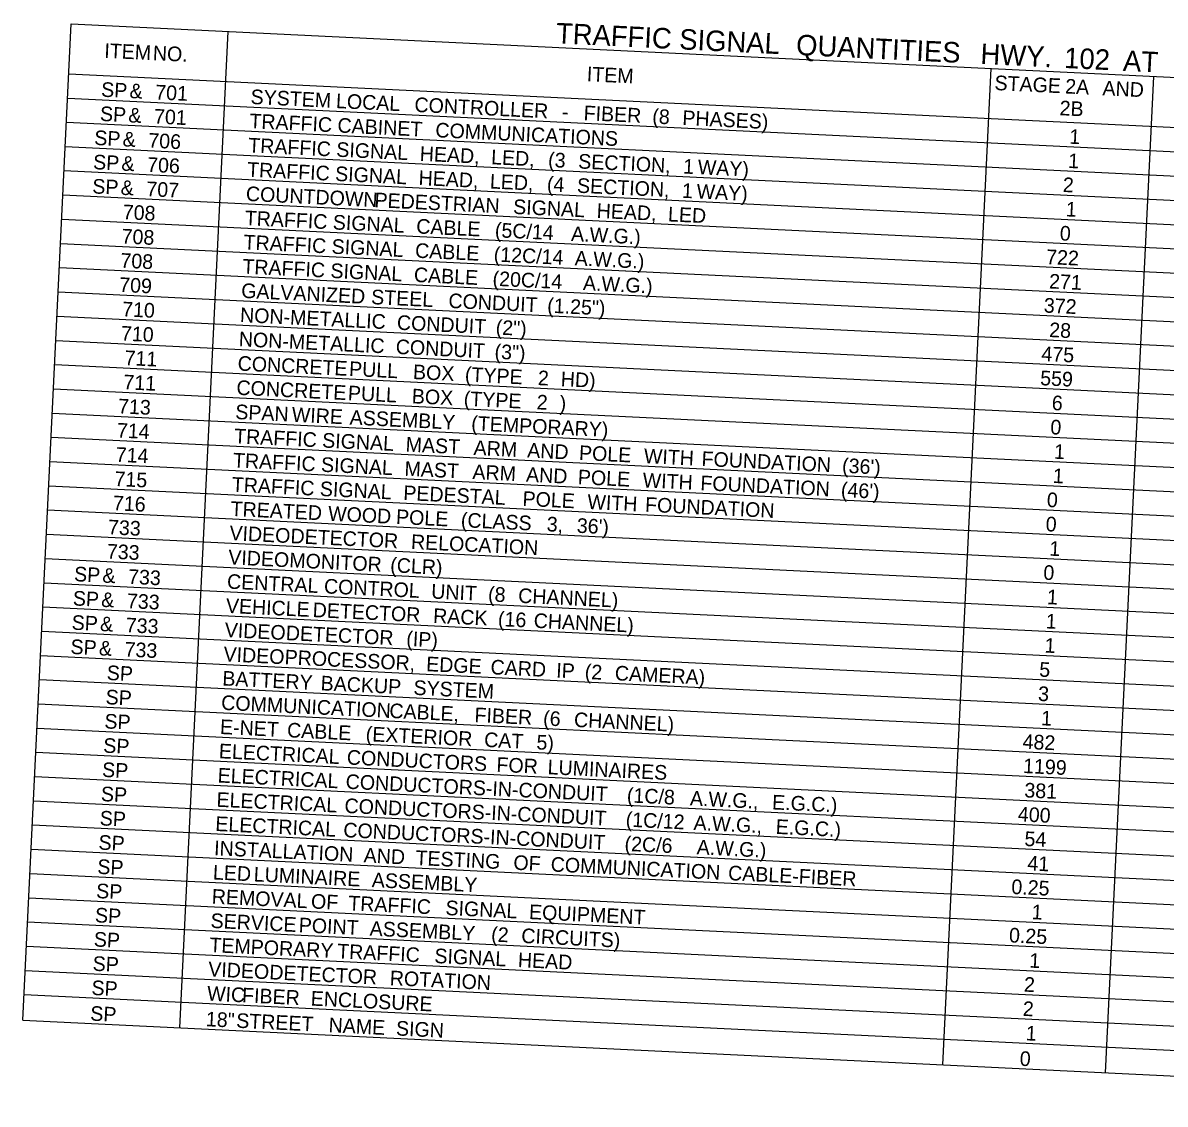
# Model space of a CAD drawing. Extents: x 669100 to 670801, y 741155 to 743955.
# Drawn here: x 669390.2 to 669585.2, y 743447.8 to 743632.5 of the extents above; entities that cross this region are included whole.
import ezdxf

# ---------------------------------------------------------------- set-up
doc = ezdxf.new("R2010")
doc.units = 0
doc.layers.add('R_Dimension', color=7, linetype='Continuous')

msp = doc.modelspace()

# ---------------------------------------------------------------- linework, layer by layer
at = {"layer": 'R_Dimension'}
for p, q in [((669390.25, 743462.16), (669398.51, 743632.34)), ((669398.51, 743632.34), (669693.59, 743618.01)), ((669417.03, 743460.86), (669425.29, 743631.04)), ((669398.1, 743623.82), (669693.18, 743609.49)), ((669547.28, 743454.54), (669555.55, 743624.72)), ((669575.04, 743453.19), (669583.3, 743623.37)), ((669397.9, 743619.68), (669692.97, 743605.35)), ((669397.7, 743615.54), (669692.77, 743601.21)), ((669397.49, 743611.4), (669692.57, 743597.08)), ((669397.29, 743607.27), (669692.37, 743592.94)), ((669397.09, 743603.13), (669692.17, 743588.8)), ((669396.89, 743598.99), (669691.97, 743584.66)), ((669396.69, 743594.85), (669691.77, 743580.52)), ((669396.49, 743590.71), (669691.57, 743576.38)), ((669396.29, 743586.57), (669691.37, 743572.24)), ((669396.09, 743582.43), (669691.17, 743568.1)), ((669395.89, 743578.29), (669690.96, 743563.96)), ((669395.69, 743574.15), (669690.76, 743559.83)), ((669395.49, 743570.02), (669690.56, 743555.69)), ((669395.28, 743565.88), (669690.36, 743551.55)), ((669395.08, 743561.74), (669690.16, 743547.41)), ((669394.88, 743557.6), (669689.96, 743543.27)), ((669394.68, 743553.46), (669689.76, 743539.13)), ((669394.48, 743549.32), (669689.56, 743534.99)), ((669394.28, 743545.18), (669689.36, 743530.85)), ((669394.08, 743541.04), (669689.16, 743526.71)), ((669393.88, 743536.9), (669688.95, 743522.58)), ((669393.68, 743532.77), (669688.75, 743518.44)), ((669393.48, 743528.63), (669688.55, 743514.3)), ((669393.27, 743524.49), (669688.35, 743510.16)), ((669393.07, 743520.35), (669688.15, 743506.02)), ((669392.87, 743516.21), (669687.95, 743501.88)), ((669392.67, 743512.07), (669687.75, 743497.74)), ((669392.47, 743507.93), (669687.55, 743493.6)), ((669392.27, 743503.79), (669687.35, 743489.46)), ((669392.07, 743499.65), (669687.15, 743485.33)), ((669391.87, 743495.52), (669686.94, 743481.19)), ((669391.67, 743491.38), (669686.74, 743477.05)), ((669391.47, 743487.24), (669686.54, 743472.91)), ((669391.26, 743483.1), (669686.34, 743468.77)), ((669391.06, 743478.96), (669686.14, 743464.63)), ((669390.86, 743474.82), (669685.94, 743460.49)), ((669390.66, 743470.68), (669685.74, 743456.35)), ((669390.46, 743466.54), (669685.54, 743452.22)), ((669390.25, 743462.16), (669685.33, 743447.83))]:
    msp.add_line(p, q, dxfattribs=at)

# ---------------------------------------------------------------- texts
for s, height, p in [('TRAFFIC', 3.5, (669481.19, 743629.03)), (' SIGNAL', 3.5, (669500.93, 743628.07)), ('ITEM', 2.5, (669404.11, 743626.55)), (' QUANTITIES', 3.5, (669520.88, 743627.1)), (' HWY.', 3.5, (669552.35, 743625.57)), (' NO.', 2.5, (669411.47, 743626.19)), (' 102', 3.5, (669566.63, 743624.88)), (' AT', 3.5, (669576.68, 743624.39)), ('ITEM', 2.5, (669486.47, 743622.55)), ('STAGE', 2.5, (669556.07, 743621.05)), (' 2A', 2.5, (669567.2, 743620.51)), ('SP', 2.5, (669403.57, 743619.91)), (' &', 2.5, (669407.49, 743619.72)), (' 701', 2.5, (669411.87, 743619.5)), ('SYSTEM', 2.5, (669429.08, 743618.67)), (' AND', 2.5, (669573.57, 743620.2)), (' LOCAL', 2.5, (669442.73, 743618.01)), (' CONTROLLER', 2.5, (669456.12, 743617.36)), ('2B', 2.5, (669567.17, 743616.75)), ('SP', 2.5, (669403.37, 743615.77)), (' &', 2.5, (669407.29, 743615.58)), (' 701', 2.5, (669411.67, 743615.37)), (' -', 2.5, (669481.29, 743616.13)), (' FIBER', 2.5, (669485, 743615.95)), (' (8', 2.5, (669496.72, 743615.38)), (' PHASES)', 2.5, (669501.85, 743615.13)), ('TRAFFIC', 2.5, (669428.88, 743614.53)), (' CABINET', 2.5, (669442.98, 743613.84)), (' COMMUNICATIONS', 2.5, (669459.69, 743613.03)), ('SP', 2.5, (669402.4, 743611.67)), (' &', 2.5, (669406.31, 743611.48)), (' 706', 2.5, (669410.69, 743611.26)), ('1', 2.5, (669568.83, 743611.88)), ('TRAFFIC', 2.5, (669428.68, 743610.39)), (' SIGNAL', 2.5, (669442.78, 743609.71)), (' HEAD,', 2.5, (669457.03, 743609.01)), ('SP', 2.5, (669402.2, 743607.53)), (' &', 2.5, (669406.11, 743607.34)), (' 706', 2.5, (669410.49, 743607.13)), (' LED,', 2.5, (669469.21, 743608.42)), (' (3', 2.5, (669478.94, 743607.95)), (' SECTION,', 2.5, (669484.07, 743607.7)), ('1', 2.5, (669568.63, 743607.74)), ('TRAFFIC', 2.5, (669428.48, 743606.25)), (' SIGNAL', 2.5, (669442.58, 743605.57)), (' 1', 2.5, (669501.98, 743606.83)), (' WAY)', 2.5, (669504.48, 743606.71)), ('SP', 2.5, (669402.06, 743603.39)), (' &', 2.5, (669405.98, 743603.2)), (' 707', 2.5, (669410.36, 743602.98)), (' HEAD,', 2.5, (669456.83, 743604.87)), (' LED,', 2.5, (669469, 743604.28)), (' (4', 2.5, (669478.74, 743603.81)), (' SECTION,', 2.5, (669483.87, 743603.56)), ('2', 2.5, (669567.72, 743603.64)), ('COUNTDOWN', 2.5, (669428.28, 743602.11)), (' PEDESTRIAN', 2.5, (669449.3, 743601.09)), (' 1', 2.5, (669501.78, 743602.69)), (' WAY)', 2.5, (669504.28, 743602.57)), (' SIGNAL', 2.5, (669472.97, 743599.94)), (' HEAD,', 2.5, (669487.23, 743599.25)), ('1', 2.5, (669568.23, 743599.47)), ('708', 2.5, (669407.26, 743598.99)), ('TRAFFIC', 2.5, (669428.08, 743597.97)), (' SIGNAL', 2.5, (669442.18, 743597.29)), (' LED', 2.5, (669499.4, 743598.66)), (' CABLE', 2.5, (669456.43, 743596.6)), (' (5C/14', 2.5, (669469.86, 743595.95)), (' A.W.G.)', 2.5, (669482.86, 743595.31)), ('0', 2.5, (669567.21, 743595.37)), ('708', 2.5, (669407.06, 743594.85)), ('TRAFFIC', 2.5, (669427.88, 743593.84)), (' SIGNAL', 2.5, (669441.98, 743593.15)), (' CABLE', 2.5, (669456.23, 743592.46)), (' (12C/14', 2.5, (669469.66, 743591.81)), ('722', 2.5, (669564.88, 743591.33)), ('708', 2.5, (669406.86, 743590.71)), ('TRAFFIC', 2.5, (669427.68, 743589.7)), (' A.W.G.)', 2.5, (669483.48, 743591.14)), (' SIGNAL', 2.5, (669441.78, 743589.01)), (' CABLE', 2.5, (669456.03, 743588.32)), (' (20C/14', 2.5, (669469.46, 743587.67)), ('709', 2.5, (669406.65, 743586.57)), ('GALVANIZED', 2.5, (669427.48, 743585.56)), (' A.W.G.)', 2.5, (669484.89, 743586.92)), ('271', 2.5, (669565.38, 743587.16)), (' STEEL', 2.5, (669448.73, 743584.53)), (' CONDUIT', 2.5, (669461.92, 743583.88)), ('710', 2.5, (669407.15, 743582.4)), (' (1.25")', 2.5, (669478.79, 743583.07)), ('372', 2.5, (669564.48, 743583.05)), ('NON-METALLIC', 2.5, (669427.28, 743581.42)), (' CONDUIT', 2.5, (669453.13, 743580.16)), ('710', 2.5, (669406.95, 743578.26)), (' (2")', 2.5, (669470, 743579.34)), ('28', 2.5, (669565.4, 743578.86)), ('NON-METALLIC', 2.5, (669427.07, 743577.28)), (' CONDUIT', 2.5, (669452.93, 743576.02)), ('711', 2.5, (669407.57, 743574.08)), (' (3")', 2.5, (669469.8, 743575.2)), ('475', 2.5, (669564.07, 743574.78)), ('CONCRETE', 2.5, (669426.87, 743573.14)), (' PULL', 2.5, (669444.96, 743572.26)), ('711', 2.5, (669407.37, 743569.94)), (' BOX', 2.5, (669455.87, 743571.73)), (' (TYPE', 2.5, (669464.74, 743571.3)), (' 2', 2.5, (669477.19, 743570.7)), (' HD)', 2.5, (669481.1, 743570.51)), ('559', 2.5, (669563.86, 743570.64)), ('CONCRETE', 2.5, (669426.67, 743569)), (' PULL', 2.5, (669444.76, 743568.12)), (' BOX', 2.5, (669455.67, 743567.59)), (' (TYPE', 2.5, (669464.54, 743567.16)), (' 2', 2.5, (669476.99, 743566.56)), (' )', 2.5, (669480.9, 743566.37)), ('6', 2.5, (669565.84, 743566.39)), ('713', 2.5, (669406.46, 743565.83)), ('SPAN', 2.5, (669426.47, 743564.86)), (' WIRE', 2.5, (669435.18, 743564.44)), (' ASSEMBLY', 2.5, (669445.07, 743563.96)), (' (TEMPORARY)', 2.5, (669465.82, 743562.95)), ('0', 2.5, (669565.6, 743562.26)), ('714', 2.5, (669406.26, 743561.7)), ('TRAFFIC', 2.5, (669426.27, 743560.72)), (' SIGNAL', 2.5, (669440.37, 743560.04)), (' MAST', 2.5, (669454.62, 743559.35)), (' ARM', 2.5, (669466.22, 743558.78)), (' AND', 2.5, (669475.37, 743558.34)), ('714', 2.5, (669406.06, 743557.56)), ('TRAFFIC', 2.5, (669426.07, 743556.59)), (' POLE', 2.5, (669484.21, 743557.91)), (' WITH', 2.5, (669495.28, 743557.37)), (' FOUNDATION', 2.5, (669505.13, 743556.89)), ('1', 2.5, (669566.22, 743558.08)), (' SIGNAL', 2.5, (669440.17, 743555.9)), (' MAST', 2.5, (669454.42, 743555.21)), (' ARM', 2.5, (669466.02, 743554.65)), (" (36')", 2.5, (669529.12, 743555.73)), ('715', 2.5, (669405.85, 743553.42)), ('TRAFFIC', 2.5, (669425.87, 743552.45)), (' AND', 2.5, (669475.17, 743554.2)), (' POLE', 2.5, (669484.01, 743553.77)), (' WITH', 2.5, (669495.08, 743553.23)), (' FOUNDATION', 2.5, (669504.93, 743552.76)), ('1', 2.5, (669566.02, 743553.94)), (' SIGNAL', 2.5, (669439.97, 743551.76)), (' PEDESTAL', 2.5, (669454.22, 743551.07)), (" (46')", 2.5, (669528.92, 743551.59)), ('716', 2.5, (669405.58, 743549.28)), ('TREATED', 2.5, (669425.67, 743548.31)), (' POLE', 2.5, (669474.57, 743550.08)), (' WITH', 2.5, (669485.64, 743549.54)), (' FOUNDATION', 2.5, (669495.49, 743549.07)), ('0', 2.5, (669565, 743549.84)), (' WOOD', 2.5, (669441.38, 743547.54)), (' POLE', 2.5, (669452.98, 743546.98)), (' (CLASS', 2.5, (669464.05, 743546.44)), ('733', 2.5, (669404.74, 743545.17)), (' 3,', 2.5, (669478.7, 743545.73)), (" 36')", 2.5, (669483.83, 743545.48)), ('0', 2.5, (669564.8, 743545.7)), ('VIDEO', 2.5, (669425.47, 743544.17)), (' DETECTOR', 2.5, (669434.96, 743543.71)), (' RELOCATION', 2.5, (669455.53, 743542.71)), ('733', 2.5, (669404.54, 743541.04)), ('1', 2.5, (669565.42, 743541.52)), ('VIDEO', 2.5, (669425.27, 743540.03)), (' MONITOR', 2.5, (669434.76, 743539.57)), (' (CLR)', 2.5, (669451.99, 743538.73)), ('SP', 2.5, (669398.95, 743537.16)), (' &', 2.5, (669402.86, 743536.97)), (' 733', 2.5, (669407.24, 743536.76)), ('0', 2.5, (669564.4, 743537.42)), ('CENTRAL', 2.5, (669425.06, 743535.89)), (' CONTROL', 2.5, (669440.68, 743535.13)), ('SP', 2.5, (669398.74, 743533.02)), (' &', 2.5, (669402.66, 743532.83)), (' UNIT', 2.5, (669458.98, 743534.24)), (' (8', 2.5, (669468.69, 743533.77)), (' CHANNEL)', 2.5, (669473.83, 743533.52)), ('1', 2.5, (669565.01, 743533.24)), (' 733', 2.5, (669407.04, 743532.62)), ('VEHICLE', 2.5, (669424.86, 743531.75)), (' DETECTOR', 2.5, (669438.75, 743531.08)), ('SP', 2.5, (669398.54, 743528.88)), (' RACK', 2.5, (669459.31, 743530.08)), (' (16', 2.5, (669470.38, 743529.54)), (' CHANNEL)', 2.5, (669476.48, 743529.25)), ('1', 2.5, (669564.81, 743529.1)), (' &', 2.5, (669402.46, 743528.69)), (' 733', 2.5, (669406.84, 743528.48)), ('VIDEO', 2.5, (669424.66, 743527.61)), (' DETECTOR', 2.5, (669434.16, 743527.15)), (' (IP)', 2.5, (669454.73, 743526.15)), ('1', 2.5, (669564.61, 743524.97)), ('SP', 2.5, (669398.34, 743524.74)), (' &', 2.5, (669402.26, 743524.55)), (' 733', 2.5, (669406.64, 743524.34)), ('VIDEO', 2.5, (669424.46, 743523.47)), (' PROCESSOR,', 2.5, (669433.96, 743523.01)), (' EDGE', 2.5, (669458.12, 743521.84)), (' CARD', 2.5, (669469.11, 743521.31)), ('SP', 2.5, (669404.53, 743520.29)), ('BATTERY', 2.5, (669424.26, 743519.34)), (' IP', 2.5, (669480.32, 743520.76)), (' (2', 2.5, (669485.2, 743520.52)), (' CAMERA)', 2.5, (669490.33, 743520.28)), ('5', 2.5, (669563.7, 743520.86)), (' BACKUP', 2.5, (669440.11, 743518.57)), (' SYSTEM', 2.5, (669455.96, 743517.8)), ('SP', 2.5, (669404.33, 743516.15)), ('COMMUNICATION', 2.5, (669424.06, 743515.2)), ('3', 2.5, (669563.5, 743516.72)), (' CABLE,', 2.5, (669451.84, 743513.85)), ('SP', 2.5, (669404.13, 743512.02)), (' FIBER', 2.5, (669466.37, 743513.14)), (' (6', 2.5, (669478.09, 743512.57)), (' CHANNEL)', 2.5, (669483.36, 743512.32)), ('1', 2.5, (669564.01, 743512.55)), ('E-NET', 2.5, (669423.86, 743511.06)), (' CABLE', 2.5, (669434.38, 743510.55)), (' (EXTERIOR', 2.5, (669447.81, 743509.89)), ('SP', 2.5, (669403.93, 743507.88)), (' CAT', 2.5, (669468.02, 743508.91)), (' 5)', 2.5, (669476.95, 743508.48)), ('482', 2.5, (669560.86, 743508.55)), ('ELECTRICAL', 2.5, (669423.66, 743506.92)), (' CONDUCTORS', 2.5, (669444.58, 743505.9)), ('SP', 2.5, (669403.73, 743503.74)), (' FOR', 2.5, (669470.12, 743504.66)), (' LUMINAIRES', 2.5, (669478.85, 743504.24)), ('1199', 2.5, (669560.94, 743504.4)), ('ELECTRICAL', 2.5, (669423.46, 743502.78)), (' CONDUCTORS-IN-CONDUIT', 2.5, (669444.38, 743501.76)), ('SP', 2.5, (669403.53, 743499.6)), ('381', 2.5, (669561.16, 743500.24)), ('ELECTRICAL', 2.5, (669423.26, 743498.64)), (' (1C/8', 2.5, (669492.39, 743499.43)), (' A.W.G.,', 2.5, (669503.15, 743498.91)), (' E.G.C.)', 2.5, (669517.17, 743498.23)), (' CONDUCTORS-IN-CONDUIT', 2.5, (669444.18, 743497.63)), ('400', 2.5, (669560.05, 743496.15)), ('SP', 2.5, (669403.33, 743495.46)), ('ELECTRICAL', 2.5, (669423.06, 743494.5)), (' (1C/12', 2.5, (669492.19, 743495.29)), (' A.W.G.,', 2.5, (669503.77, 743494.73)), (' E.G.C.)', 2.5, (669517.79, 743494.05)), (' CONDUCTORS-IN-CONDUIT', 2.5, (669443.98, 743493.49)), ('54', 2.5, (669561.18, 743491.94)), ('SP', 2.5, (669403.12, 743491.32)), ('INSTALLATION', 2.5, (669422.85, 743490.36)), (' (2C/6', 2.5, (669491.99, 743491.15)), (' A.W.G.)', 2.5, (669504.3, 743490.56)), (' AND', 2.5, (669447.45, 743489.17)), (' TESTING', 2.5, (669456.3, 743488.74)), (' OF', 2.5, (669473.01, 743487.93)), ('SP', 2.5, (669402.92, 743487.18)), ('LED', 2.5, (669422.65, 743486.22)), (' COMMUNICATION', 2.5, (669479.38, 743487.62)), (' CABLE-FIBER', 2.5, (669509.66, 743486.15)), ('41', 2.5, (669561.68, 743487.77)), (' LUMINAIRE', 2.5, (669428.69, 743485.93)), (' ASSEMBLY', 2.5, (669448.84, 743484.95)), ('SP', 2.5, (669402.72, 743483.04)), ('REMOVAL', 2.5, (669422.45, 743482.09)), ('0.25', 2.5, (669558.94, 743483.75)), (' OF', 2.5, (669438.46, 743481.31)), (' TRAFFIC', 2.5, (669444.83, 743481)), (' SIGNAL', 2.5, (669461.42, 743480.19)), ('SP', 2.5, (669402.52, 743478.9)), (' EQUIPMENT', 2.5, (669475.68, 743479.5)), ('1', 2.5, (669562.4, 743479.44)), ('SERVICE', 2.5, (669422.25, 743477.95)), (' POINT', 2.5, (669436.37, 743477.26)), (' ASSEMBLY', 2.5, (669448.48, 743476.67)), ('SP', 2.5, (669402.32, 743474.77)), (' (2', 2.5, (669469.22, 743475.67)), (' CIRCUITS)', 2.5, (669474.36, 743475.42)), ('0.25', 2.5, (669558.54, 743475.48)), ('TEMPORARY', 2.5, (669422.05, 743473.81)), (' TRAFFIC', 2.5, (669442.93, 743472.79)), ('SP', 2.5, (669402.12, 743470.63)), (' SIGNAL', 2.5, (669459.53, 743471.99)), (' HEAD', 2.5, (669473.78, 743471.3)), ('1', 2.5, (669562, 743471.16)), ('VIDEO', 2.5, (669421.85, 743469.67)), (' DETECTOR', 2.5, (669431.35, 743469.21)), ('SP', 2.5, (669401.92, 743466.49)), (' ROTATION', 2.5, (669451.91, 743468.21)), ('2', 2.5, (669561.09, 743467.06)), ('WIC', 2.5, (669421.65, 743465.53)), (' FIBER', 2.5, (669426.7, 743465.28)), (' ENCLOSURE', 2.5, (669438.42, 743464.72)), ('2', 2.5, (669560.89, 743462.92)), ('SP', 2.5, (669401.71, 743462.11)), ('18"', 2.5, (669421.44, 743461.15)), (' STREET', 2.5, (669425.7, 743460.94)), (' NAME', 2.5, (669441.47, 743460.17)), (' SIGN', 2.5, (669452.97, 743459.62)), ('1', 2.5, (669561.4, 743458.74)), ('0', 2.5, (669560.37, 743454.4))]:
    msp.add_text(s, height=height, rotation=357.2199, dxfattribs=at).set_placement(p)

doc.saveas('drawing.dxf')
